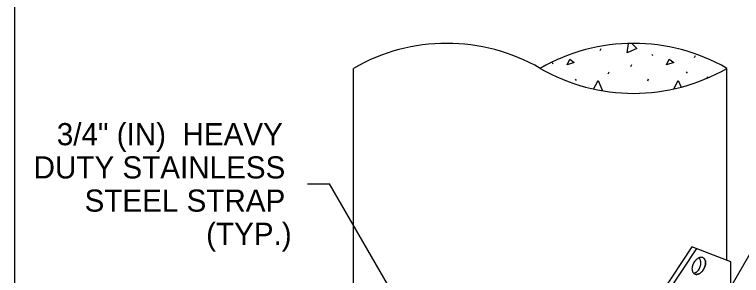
# Model space of a CAD drawing. Extents: x 99862 to 103680, y 99470 to 102076.
# Drawn here: x 99862 to 100387, y 100881 to 101070 of the extents above; entities that cross this region are included whole.
import ezdxf

# ---------------------------------------------------------------- set-up
doc = ezdxf.new("R2010")
doc.units = 0
for name, color, linetype in [('Level 1', 7, 'Continuous'), ('Level 10', 7, 'Continuous'), ('Level 11', 7, 'Continuous'), ('Level 13', 7, 'Continuous'), ('Level 15', 7, 'Continuous'), ('Level 20', 7, 'Continuous'), ('Level 9', 7, 'Continuous')]:
    doc.layers.add(name, color=color, linetype=linetype)

msp = doc.modelspace()

# ---------------------------------------------------------------- linework, layer by layer
at = {"layer": 'Level 1'}
msp.add_lwpolyline([(99862, 99999.5), (103151, 99999.5), (103151, 102075.5), (99862, 102075.5)], close=True, dxfattribs=at)
at = {"layer": 'Level 10'}
for p, q in [((100106.9, 100845.52), (100106.9, 101030.87)), ((100376.8, 100892.23), (100376.8, 101030.97))]:
    msp.add_line(p, q, dxfattribs=at)
for centre, start, end in [((100174.51, 100914.18), 60, 120.0874), ((100309.37, 100914.18), 60, 120), ((100309.37, 101147.76), 240, 300)]:
    msp.add_arc(centre, 134.86, start, end, dxfattribs=at)
at = {"layer": 'Level 11'}
for p, q in [((100285.28, 101043.8), (100285.92, 101045.24)), ((100322.55, 101041.29), (100323.19, 101040.34)), ((100353.46, 101038.78), (100354.1, 101040.22)), ((100250.5, 101035.14), (100251.14, 101034.18)), ((100307.49, 101032.28), (100308.13, 101033.72)), ((100291.11, 101027.11), (100291.75, 101028.55)), ((100347.51, 101028.38), (100348.14, 101027.43)), ((100267.22, 101023.13), (100267.86, 101022.17)), ((100319.6, 101021.92), (100320.24, 101023.36)), ((100362.36, 101023.7), (100363, 101025.14))]:
    msp.add_line(p, q, dxfattribs=at)
for points in [[(100304.73, 101042.14), (100305.68, 101048.99)], [(100308.17, 101049.03), (100311.72, 101045.37), (100304.88, 101042.2)], [(100261.31, 101033.57), (100263.22, 101037.56), (100266.42, 101035.17), (100261.31, 101033.57)], [(100333.31, 101033.57), (100335.22, 101037.56), (100338.42, 101035.17), (100333.31, 101033.57)], [(100280.5, 101016.03), (100283.7, 101022.08), (100286.97, 101014.77)], [(100338.44, 101016.07), (100341.62, 101022.08), (100343.73, 101017.35)]]:
    msp.add_lwpolyline(points, dxfattribs=at)
at = {"layer": 'Level 13'}
for p, q in [((100351.52, 100902.01), (100329.23, 100868.49)), ((100354.95, 100900.68), (100332.13, 100866.35)), ((100379.6, 100891.15), (100351.52, 100902.01)), ((100379.6, 100849.77), (100379.6, 100891.15))]:
    msp.add_line(p, q, dxfattribs=at)
at = {"layer": 'Level 15'}
for p, q in [((100073.75, 100947.4), (100089.75, 100947.4)), ((100158.74, 100827.92), (100089.75, 100947.4)), ((100362.38, 100843.21), (100412.23, 100929.65))]:
    msp.add_line(p, q, dxfattribs=at)
at = {"layer": 'Level 9'}
for points in [[(100359.63, 100894.1), (100359.56, 100894.14), (100359.47, 100894.17), (100359.16, 100894.29), (100358.72, 100894.37), (100358.71, 100894.38), (100358.26, 100894.4), (100358.13, 100894.39), (100357.69, 100894.34), (100357.65, 100894.33), (100357.15, 100894.21), (100356.65, 100894.03), (100356.6, 100894.01), (100356.51, 100893.97), (100356, 100893.7), (100355.51, 100893.39), (100355.01, 100893.01), (100354.88, 100892.9), (100354.46, 100892.51), (100354.41, 100892.47), (100353.96, 100891.99), (100353.67, 100891.63), (100353.54, 100891.47), (100353.51, 100891.42), (100353.43, 100891.32), (100353.05, 100890.76), (100352.71, 100890.18), (100352.71, 100890.17), (100352.41, 100889.56), (100352.33, 100889.39), (100352.12, 100888.84), (100352.09, 100888.77), (100351.89, 100888.14), (100351.75, 100887.51), (100351.74, 100887.47), (100351.72, 100887.34), (100351.64, 100886.72), (100351.61, 100886.13), (100351.61, 100886.12), (100351.64, 100885.53), (100351.66, 100885.38), (100351.74, 100884.9), (100351.75, 100884.83), (100351.9, 100884.33), (100352.1, 100883.85), (100352.11, 100883.83), (100352.17, 100883.73), (100352.42, 100883.33), (100352.72, 100882.99), (100352.73, 100882.97), (100353.07, 100882.67), (100353.17, 100882.6), (100353.51, 100882.4), (100353.51, 100882.4)], [(100356.57, 100893.99), (100356.51, 100893.97), (100356, 100893.7), (100355.51, 100893.39), (100355.01, 100893.01), (100354.88, 100892.9), (100354.46, 100892.51), (100354.41, 100892.47), (100353.96, 100891.99), (100353.54, 100891.47), (100353.51, 100891.42), (100353.43, 100891.32), (100353.05, 100890.76), (100352.71, 100890.18), (100352.71, 100890.17), (100352.41, 100889.56), (100352.33, 100889.39), (100352.12, 100888.84), (100352.09, 100888.77), (100351.89, 100888.14), (100351.75, 100887.51), (100351.74, 100887.47), (100351.72, 100887.34), (100351.64, 100886.72), (100351.61, 100886.13), (100351.61, 100886.12), (100351.64, 100885.53), (100351.66, 100885.38), (100351.74, 100884.9), (100351.75, 100884.83), (100351.9, 100884.33), (100352.1, 100883.85), (100352.11, 100883.83), (100352.17, 100883.73), (100352.42, 100883.33), (100352.72, 100882.99), (100352.73, 100882.97), (100353.07, 100882.67), (100353.17, 100882.6), (100353.51, 100882.4), (100353.56, 100882.37)], [(100359.67, 100894.08), (100360.04, 100893.85), (100360.37, 100893.56), (100360.39, 100893.54), (100360.66, 100893.22), (100360.73, 100893.11), (100360.96, 100892.71), (100360.96, 100892.7), (100361.15, 100892.24), (100361.29, 100891.74), (100361.31, 100891.66), (100361.32, 100891.59), (100361.4, 100891.04), (100361.43, 100890.43), (100361.4, 100889.82), (100361.33, 100889.2), (100361.31, 100889.09), (100361.2, 100888.57), (100361.16, 100888.39), (100360.97, 100887.75), (100360.96, 100887.7), (100360.74, 100887.12), (100360.47, 100886.5), (100360.39, 100886.34), (100360.38, 100886.34), (100360.06, 100885.74), (100359.69, 100885.17), (100359.63, 100885.08), (100359.47, 100884.87), (100359.3, 100884.64), (100359.18, 100884.5), (100358.74, 100884.01), (100358.71, 100883.98), (100358.29, 100883.57), (100357.81, 100883.18), (100357.69, 100883.09), (100357.68, 100883.08), (100357.18, 100882.76), (100356.68, 100882.5), (100356.6, 100882.47), (100356.17, 100882.3), (100356.03, 100882.26), (100355.53, 100882.14), (100355.5, 100882.14), (100355.04, 100882.09), (100354.57, 100882.1), (100354.46, 100882.11), (100354.44, 100882.11), (100353.99, 100882.21), (100353.67, 100882.33), (100353.56, 100882.37)], [(100356.66, 100885.74), (100356.98, 100886.34), (100356.99, 100886.34), (100357.07, 100886.5), (100357.34, 100887.12), (100357.56, 100887.7), (100357.57, 100887.75), (100357.76, 100888.39), (100357.8, 100888.57), (100357.91, 100889.09), (100357.93, 100889.2), (100358, 100889.82), (100358.03, 100890.43), (100358, 100891.04), (100357.92, 100891.59), (100357.91, 100891.66), (100357.89, 100891.74), (100357.75, 100892.24), (100357.56, 100892.7), (100357.56, 100892.71), (100357.33, 100893.11), (100357.26, 100893.22), (100356.99, 100893.54), (100356.97, 100893.56), (100356.64, 100893.85), (100356.27, 100894.08), (100356.27, 100894.08)], [(100360.06, 100885.74), (100360.38, 100886.34), (100360.39, 100886.34), (100360.47, 100886.5), (100360.74, 100887.12), (100360.96, 100887.7), (100360.97, 100887.75), (100361.16, 100888.39), (100361.2, 100888.57), (100361.31, 100889.09), (100361.33, 100889.2), (100361.4, 100889.82), (100361.43, 100890.43), (100361.4, 100891.04), (100361.32, 100891.59), (100361.31, 100891.66), (100361.29, 100891.74), (100361.15, 100892.24), (100360.96, 100892.7), (100360.96, 100892.71), (100360.73, 100893.11), (100360.66, 100893.22), (100360.39, 100893.54), (100360.37, 100893.56), (100360.04, 100893.85), (100359.67, 100894.08), (100359.67, 100894.08)], [(100352.89, 100882.8), (100353.2, 100882.9), (100353.59, 100883.06), (100353.62, 100883.07), (100353.7, 100883.1), (100354.2, 100883.36), (100354.7, 100883.68), (100354.71, 100883.69), (100354.83, 100883.78), (100355.31, 100884.17), (100355.74, 100884.58), (100355.77, 100884.61), (100356.2, 100885.1), (100356.32, 100885.24), (100356.78, 100885.86)], [(100353.56, 100882.37), (100353.56, 100882.37), (100353.99, 100882.21), (100354.44, 100882.11), (100354.46, 100882.11), (100354.57, 100882.1), (100355.04, 100882.09), (100355.5, 100882.14), (100355.53, 100882.14), (100356.03, 100882.26), (100356.17, 100882.3), (100356.57, 100882.46), (100356.6, 100882.47), (100356.68, 100882.5), (100357.18, 100882.76), (100357.68, 100883.08), (100357.69, 100883.09), (100357.81, 100883.18), (100358.29, 100883.57), (100358.71, 100883.98), (100358.74, 100884.01), (100359.18, 100884.5), (100359.3, 100884.64), (100359.63, 100885.08), (100359.69, 100885.17), (100360.06, 100885.74)]]:
    msp.add_lwpolyline(points, dxfattribs=at)

# ---------------------------------------------------------------- texts
at = {"layer": 'Level 20'}
for s, p in [('3/4" (IN)  HEAVY ', (99892.55, 100975.4)), ('DUTY STAINLESS ', (99875.8, 100951.4)), ('STEEL STRAP ', (99912.62, 100927.4)), ('(TYP.)', (100000.48, 100903.4))]:
    msp.add_text(s, height=16, dxfattribs=at).set_placement(p)

doc.saveas('drawing.dxf')
